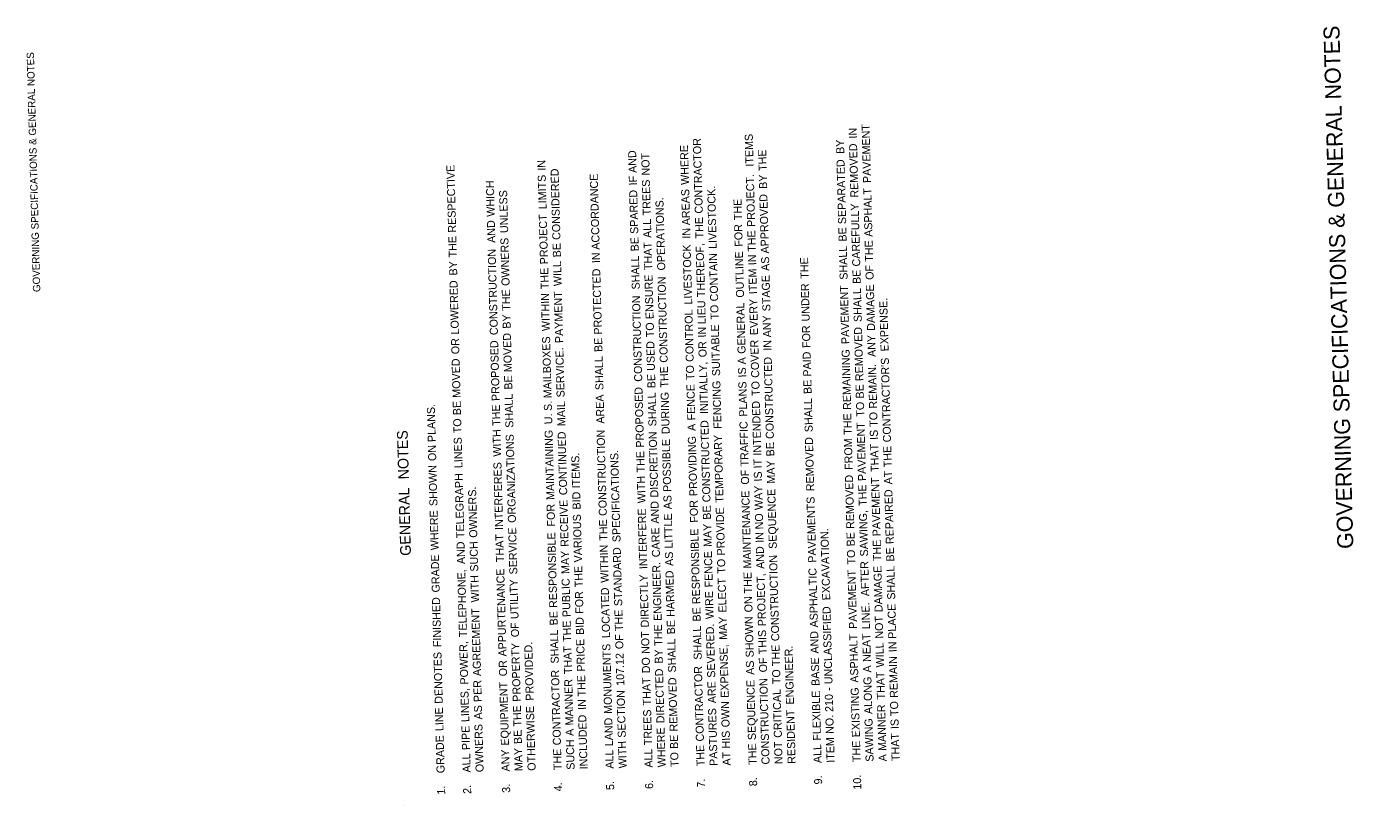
# Model space of a CAD drawing. Extents: x 1930579 to 1931706, y 595585 to 597808.
# Drawn here: x 1930711 to 1931706, y 597224 to 597808 of the extents above; entities that cross this region are included whole.
import ezdxf

# ---------------------------------------------------------------- set-up
doc = ezdxf.new("R2010")
doc.units = 0
for name, color, linetype in [('Default', 7, 'Continuous'), ('R_Annotation', 7, 'Continuous'), ('R_Border', 7, 'Continuous')]:
    doc.layers.add(name, color=color, linetype=linetype)

msp = doc.modelspace()

# ---------------------------------------------------------------- linework, layer by layer
at = {"layer": 'Default'}
msp.add_line((1930993.47, 597224.34), (1930993.47, 597224.34), dxfattribs=at)

# ---------------------------------------------------------------- texts
for s, height, p in [(' PAVEMENT', 6, (1931344.1, 597688.76)), (' CONTRACTOR', 6, (1931217.92, 597665.82)), ('  ITEMS', 6, (1931256.04, 597698.84)), (' BY', 6, (1931324, 597710.57)), (' IN', 6, (1931333.45, 597722.07)), (' AND', 6, (1931168.33, 597696.32)), (' NOT', 6, (1931178.14, 597694.36)), (' WHERE', 6, (1931207.58, 597687.37)), (' THE', 6, (1931265.82, 597697.82)), (' REMOVED', 6, (1931334.64, 597677.81)), (' RESPECTIVE', 6, (1931032.98, 597651.55)), (' IN', 6, (1931100.01, 597697.97)), (' SEPARATED', 6, (1931325.42, 597657.92)), (' LIMITS', 6, (1931100.79, 597669.08)), (' CONSIDERED', 6, (1931111.16, 597646.1)), (' ACCORDANCE', 6, (1931140.62, 597638.73)), (' IF', 6, (1931168.58, 597686.94)), (' TREES', 6, (1931178.94, 597664.53)), (' PROJECT.', 6, (1931257.2, 597655.8)), (' BY', 6, (1931266.19, 597684.38)), (' WHICH', 6, (1931061.92, 597663.46)), (' UNLESS', 6, (1931072, 597651.25)), (' SPARED', 6, (1931169.56, 597650.59)), (' AREAS', 6, (1931208.4, 597657.06)), (' LIVESTOCK.', 6, (1931228.38, 597639.37)), (' ASPHALT', 6, (1931345.18, 597648.4)), (' OPERATIONS.', 6, (1931189.8, 597623.19)), (' THE', 6, (1931247.31, 597660.92)), (' APPROVED', 6, (1931267.49, 597635.92)), (' CAREFULLY', 6, (1931336.02, 597626.18)), (' PROJECT', 6, (1931101.89, 597627.8)), (' ALL', 6, (1931179.39, 597647.59)), (' THE', 6, (1931218.42, 597647.17)), (' AND', 6, (1931062.45, 597643.89)), (' IN', 6, (1931208.67, 597647.04)), (' FOR', 6, (1931247.84, 597641.01)), (' THE', 6, (1931257.7, 597637.16)), (' BE', 6, (1931325.77, 597644.86)), (' THE', 6, (1931033.48, 597632.91)), (' OWNERS', 6, (1931073.07, 597611.65)), (' BE', 6, (1931111.51, 597633.04)), (' BE', 6, (1931169.91, 597637.53)), (' THAT', 6, (1931180.04, 597623.55)), (' LIVESTOCK', 6, (1931209.99, 597597.69)), (' THEREOF,', 6, (1931219.6, 597603.22)), (' SHALL', 6, (1931326.53, 597616.28)), (' THE', 6, (1931345.68, 597629.76)), (' CONSTRUCTION', 6, (1931064.31, 597574.73)), (' IN', 6, (1931140.88, 597628.71)), (' SHALL', 6, (1931170.68, 597608.94)), (' CONTAIN', 6, (1931229.44, 597600.01)), (' OUTLINE', 6, (1931248.87, 597602.81)), (' IN', 6, (1931257.97, 597627.14)), (' AS', 6, (1931267.84, 597622.85)), (' THE', 6, (1931297.25, 597617.01)), (' BY', 6, (1931033.84, 597619.46)), (' THE', 6, (1931102.4, 597609.16)), (' WILL', 6, (1931112.09, 597611.46)), (' PROTECTED', 6, (1931142.32, 597575.14)), (' ITEM', 6, (1931258.55, 597605.42)), (' BE', 6, (1931336.37, 597613.12)), (' OF', 6, (1931346.04, 597616.18)), (' LOWERED', 6, (1931035.03, 597575.21)), (' ENSURE', 6, (1931181.02, 597586.74)), (' CONSTRUCTION', 6, (1931191.66, 597554.04)), (' STAGE', 6, (1931268.65, 597592.56)), (' UNDER', 6, (1931298.11, 597584.99)), (' PAVEMENT', 6, (1931327.83, 597568.01)), (' DAMAGE', 6, (1931347.07, 597577.97)), (' THE', 6, (1931073.57, 597593)), (' WITHIN', 6, (1931103.24, 597577.73)), (' PAYMENT', 6, (1931113.23, 597568.78)), (' CONSTRUCTION', 6, (1931172.53, 597539.79)), (' EVERY', 6, (1931259.38, 597574.74)), (' SHALL', 6, (1931337.14, 597584.54)), (' EXPENSE.', 6, (1931357.24, 597562.55)), (' CONTROL', 6, (1931211.15, 597554.69)), (' LIEU', 6, (1931220.14, 597582.94)), (' TO', 6, (1931229.8, 597586.42)), (' GENERAL', 6, (1931250, 597560.73)), (' BY', 6, (1931073.93, 597579.56)), (' TO', 6, (1931181.39, 597573.15)), (' SUITABLE', 6, (1931230.94, 597544.02)), (' ANY', 6, (1931269.17, 597573.06)), (' FOR', 6, (1931298.65, 597565.09)), (' OR', 6, (1931035.43, 597560.43)), (' MOVED', 6, (1931074.8, 597546.94)), (' MAILBOXES', 6, (1931104.59, 597527.4)), (' BE', 6, (1931142.67, 597562.08)), (' IN', 6, (1931220.41, 597572.92)), (' REMOVED', 6, (1931338.33, 597540.28)), ('  ANY', 6, (1931347.66, 597556.15)), (' PROPOSED', 6, (1931065.63, 597525.35)), (' SERVICE.', 6, (1931114.33, 597528.06)), (' USED', 6, (1931182.07, 597547.98)), (' OR', 6, (1931220.81, 597558.13)), (' COVER', 6, (1931260.23, 597542.72)), (' IN', 6, (1931269.44, 597563.04)), (' PAID', 6, (1931299.22, 597543.65)), (' REMAINING', 6, (1931329.15, 597518.72)), (' MOVED', 6, (1931036.3, 597527.81)), (' SHALL', 6, (1931143.44, 597533.5)), (' TO', 6, (1931211.51, 597541.1)), (' INITIALLY,', 6, (1931221.95, 597515.57)), (' A', 6, (1931250.21, 597552.8)), (' CONSTRUCTED', 6, (1931271.22, 597496.9)), (' REMAIN.', 6, (1931348.64, 597519.63)), (" CONTRACTOR'S", 6, (1931359.07, 597494.34)), (' BE', 6, (1931075.16, 597533.88)), (' BE', 6, (1931182.42, 597534.92)), (' THE', 6, (1931192.16, 597535.4)), (' IS', 6, (1931250.47, 597542.99)), (' PROPOSED', 6, (1931173.86, 597490.41)), (' FENCE', 6, (1931212.32, 597510.81)), (' FENCING', 6, (1931232, 597504.5)), (' PLANS', 6, (1931251.26, 597513.62)), (' TO', 6, (1931260.6, 597529.13)), (' BE', 6, (1931299.57, 597530.59)), (' BE', 6, (1931338.68, 597527.22)), (' PLANS.', 6, (1931017.69, 597494.58)), (' BE', 6, (1931036.65, 597514.75)), (' THE', 6, (1931066.13, 597506.7)), (' SHALL', 6, (1931075.92, 597505.3)), (' S.', 6, (1931104.85, 597517.89)), (' MAIL', 6, (1931114.9, 597506.48)), (' AREA', 6, (1931144.12, 597508.34)), (' SHALL', 6, (1931183.18, 597506.34)), (' DURING', 6, (1931193.09, 597500.54)), (' INTENDED', 6, (1931261.8, 597484.41)), (' SHALL', 6, (1931300.34, 597502.01)), (' TO', 6, (1931339.04, 597513.63)), (' TO', 6, (1931037.02, 597501.16)), (' U.', 6, (1931105.11, 597507.91)), (' THE', 6, (1931329.65, 597500.08)), (' TO', 6, (1931349, 597506.04)), (' NOTES', 8, (1930997.57, 597465.89)), (' WITH', 6, (1931066.75, 597483.65)), (' MAINTAINING', 6, (1931106.64, 597451.17)), (' CONTINUED', 6, (1931116.29, 597454.78)), (' CONSTRUCTION', 6, (1931145.97, 597439.18)), (' A', 6, (1931212.54, 597502.88)), (' CONSTRUCTED', 6, (1931223.72, 597449.44)), (' TRAFFIC', 6, (1931252.27, 597476.24)), (' PAVEMENT', 6, (1931340.34, 597465.36)), (' IS', 6, (1931349.26, 597496.23)), (' LINES', 6, (1931037.72, 597475.05)), (' ORGANIZATIONS', 6, (1931077.84, 597434.03)), (' DISCRETION', 6, (1931184.61, 597453.02)), (' POSSIBLE', 6, (1931194.26, 597457.2)), (' PROVIDING', 6, (1931213.85, 597454.05)), (' TEMPORARY', 6, (1931233.49, 597449.15)), (' BE', 6, (1931271.57, 597483.84)), (' REMOVED', 6, (1931301.53, 597457.75)), (' FROM', 6, (1931330.36, 597473.71)), (' THAT', 6, (1931349.91, 597472.19)), (' ON', 6, (1931018.07, 597480.36)), (' ITEMS.', 6, (1931125.91, 597459.86)), (' SPECIFICATIONS.', 6, (1931156.25, 597419.57)), (' THE', 6, (1931174.36, 597471.76)), (' THE', 6, (1931359.57, 597475.7)), (' SHOWN', 6, (1931018.98, 597446.6)), (' INTERFERES', 6, (1931068.23, 597428.67)), (' OF', 6, (1931252.63, 597462.66)), (' IT', 6, (1931262.06, 597474.81)), (' IS', 6, (1931262.32, 597465)), (' MAY', 6, (1931272.12, 597463.42)), (' AT', 6, (1931359.91, 597462.83)), (' TELEGRAPH', 6, (1931039.13, 597422.64)), (' WITH', 6, (1931174.98, 597448.7)), (' REMOVED', 6, (1931331.55, 597429.45)), (' THE', 6, (1931340.84, 597446.72)), (' PAVEMENT', 6, (1931351.21, 597423.93)), ('GENERAL', 8, (1930999.03, 597411.59)), (' OWNERS.', 6, (1931048.88, 597422.86)), (' BID', 6, (1931126.34, 597444.01)), (' AS', 6, (1931194.61, 597444.13)), (' MAINTENANCE', 6, (1931254.32, 597399.78)), (' WAY', 6, (1931262.89, 597443.65)), (' SEQUENCE', 6, (1931273.43, 597414.5)), (' PAVEMENTS', 6, (1931302.97, 597404.16)), (' REPAIRED', 6, (1931361.11, 597418.1)), (' WHERE', 6, (1931019.87, 597413.52)), (' FOR', 6, (1931107.17, 597431.27)), (' RECEIVE', 6, (1931117.33, 597416.1)), (' INTERFERE', 6, (1931176.3, 597399.33)), (' AND', 6, (1931185.14, 597433.44)), (' FOR', 6, (1931214.38, 597434.14)), (' BE', 6, (1931224.08, 597436.38)), (' PROVIDE', 6, (1931234.55, 597409.55)), (' SAWING,', 6, (1931341.86, 597408.82)), (' VARIOUS', 6, (1931127.4, 597404.4)), (' THE', 6, (1931146.47, 597420.54)), (' LITTLE', 6, (1931195.39, 597414.78)), (' MAY', 6, (1931224.62, 597415.95)), (' NO', 6, (1931263.28, 597429.12)), (' THAT', 6, (1931068.87, 597404.63)), (' SERVICE', 6, (1931078.87, 597395.36)), (' RESPONSIBLE', 6, (1931108.81, 597370.23)), (' CARE', 6, (1931185.82, 597408.27)), (' RESPONSIBLE', 6, (1931216.02, 597373.11)), (' IN', 6, (1931263.55, 597419.1)), (' EXCAVATION.', 6, (1931313.48, 597375.94)), (' BE', 6, (1931331.9, 597416.39)), (' AND', 6, (1931039.65, 597403.06)), (' SUCH', 6, (1931049.56, 597397.46)), (' MAY', 6, (1931117.88, 597395.68)), (' WITHIN', 6, (1931147.32, 597389.11)), (' STANDARD', 6, (1931157.54, 597371.59)), (' FENCE', 6, (1931225.44, 597385.66)), (' AND', 6, (1931264.08, 597399.53)), (' TO', 6, (1931332.27, 597402.8)), (' THE', 6, (1931351.71, 597405.28)), (' BE', 6, (1931361.47, 597405.04)), (' GRADE', 6, (1931020.72, 597381.84)), (' ENGINEER.', 6, (1931187.1, 597360.58)), (' AS', 6, (1931195.75, 597401.71)), (' TO', 6, (1931234.91, 597395.95)), (' CONSTRUCTION', 6, (1931275.29, 597345.34)), ('  AFTER', 6, (1931342.72, 597376.81)), (' TELEPHONE,', 6, (1931041.12, 597348.39)), (' WITH', 6, (1931050.18, 597374.4)), (' APPURTENANCE', 6, (1931070.77, 597333.82)), (' THE', 6, (1931127.9, 597385.75)), (' DIRECTLY', 6, (1931177.48, 597355.62)), (' HARMED', 6, (1931196.77, 597363.51)), (' THE', 6, (1931254.82, 597381.14)), (' PROJECT,', 6, (1931265.23, 597356.5)), (' ASPHALTIC', 6, (1931304.27, 597355.6)), (' PAVEMENT', 6, (1931333.56, 597354.53)), (' DAMAGE', 6, (1931352.73, 597367.08)), (' SHALL', 6, (1931362.23, 597376.46)), (' UTILITY', 6, (1931079.77, 597361.9)), (' PUBLIC', 6, (1931118.75, 597363.41)), (' LOCATED', 6, (1931148.43, 597347.65)), (' WIRE', 6, (1931226.07, 597361.9)), (' ELECT', 6, (1931235.7, 597366.78)), (' FINISHED', 6, (1931021.82, 597340.84)), (' FOR', 6, (1931128.43, 597365.85)), (' ON', 6, (1931255.2, 597366.92)), (' LINE.', 6, (1931343.32, 597354.26)), (' PLACE', 6, (1931363.02, 597347.1)), (' AGREEMENT', 6, (1931051.66, 597319.15)), (' BE', 6, (1931109.16, 597357.17)), (' BID', 6, (1931128.86, 597350)), (' THE', 6, (1931158.04, 597352.95)), (' BE', 6, (1931216.37, 597360.05)), (' MAY', 6, (1931236.25, 597346.36)), (' SHOWN', 6, (1931256.11, 597333.16)), (' UNCLASSIFIED', 6, (1931315.17, 597313.06)), (' NOT', 6, (1931353.26, 597347.23)), (' OF', 6, (1931080.14, 597348.32)), (' SHALL', 6, (1931109.93, 597328.59)), (' THE', 6, (1931119.25, 597344.77)), (' THE', 6, (1931187.6, 597341.93)), (' BE', 6, (1931197.12, 597350.45)), (' SHALL', 6, (1931217.14, 597331.47)), (' SEVERED.', 6, (1931227.26, 597317.92)), (' THIS', 6, (1931265.8, 597335.52)), (' POWER,', 6, (1931042.08, 597312.81)), (' PROPERTY', 6, (1931081.43, 597299.94)), (' PROVIDED.', 6, (1931091.17, 597300.71)), (' PRICE', 6, (1931129.6, 597322.51)), (' MONUMENTS', 6, (1931149.95, 597290.82)), (' OF', 6, (1931158.4, 597339.36)), (' NOT', 6, (1931178.01, 597335.77)), (' SHALL', 6, (1931197.89, 597321.86)), (' AND', 6, (1931304.8, 597336.02)), (' ASPHALT', 6, (1931334.64, 597314.18)), (' NEAT', 6, (1931343.98, 597329.74)), (' WILL', 6, (1931353.84, 597325.65)), (' IN', 6, (1931363.29, 597337.08)), (' DENOTES', 6, (1931022.95, 597298.44)), (' THAT', 6, (1931119.89, 597320.73)), (' 107.12', 6, (1931159.14, 597311.86)), (' DO', 6, (1931178.4, 597321.25)), (' BY', 6, (1931187.96, 597328.49)), (' EXPENSE,', 6, (1931237.41, 597302.85)), (' THE', 6, (1931275.79, 597326.7)), (' ENGINEER.', 6, (1931286.32, 597297.85)), (' BASE', 6, (1931305.45, 597311.78)), (' REMAIN', 6, (1931364.21, 597302.84)), (' OR', 6, (1931071.17, 597319.03)), (' CONTRACTOR', 6, (1931111.57, 597267.24)), (' DIRECTED', 6, (1931189.16, 597283.77)), (' CONTRACTOR', 6, (1931218.78, 597270.12)), (' AS', 6, (1931256.46, 597320.09)), (' OF', 6, (1931266.16, 597321.94)), (' TO', 6, (1931276.15, 597313.11)), (' A', 6, (1931344.19, 597321.81)), (' PER', 6, (1931052.18, 597299.7)), (' EQUIPMENT', 6, (1931072.56, 597267.05)), (' MANNER', 6, (1931120.93, 597282.19)), (' THE', 6, (1931130.1, 597303.86)), (' THAT', 6, (1931179.04, 597297.2)), (' REMOVED', 6, (1931199.08, 597277.61)), (' ARE', 6, (1931227.77, 597298.81)), (' SEQUENCE', 6, (1931257.77, 597271.17)), ('CONSTRUCTION', 6, (1931267.96, 597255.11)), (' ALONG', 6, (1931345.03, 597290.67)), (' THAT', 6, (1931354.49, 597301.61)), (' LINES,', 6, (1931042.83, 597284.69)), (' SECTION', 6, (1931160.19, 597272.97)), (' CRITICAL', 6, (1931277.23, 597272.9)), (' FLEXIBLE', 6, (1931306.55, 597270.77)), (' 210', 6, (1931315.72, 597292.3)), (' -', 6, (1931315.3, 597308.2)), (' EXISTING', 6, (1931335.74, 597273.26)), (' LINE', 6, (1931023.5, 597277.93)), (' AS', 6, (1931052.53, 597286.63)), (' THE', 6, (1931081.94, 597281.3)), ('OTHERWISE', 6, (1931092.52, 597250.4)), (' IN', 6, (1931130.37, 597293.84)), (' TREES', 6, (1931179.84, 597267.37)), ('PASTURES', 6, (1931228.97, 597254.07)), (' OWN', 6, (1931238.01, 597280.73)), ('RESIDENT', 6, (1931287.45, 597255.64)), (' MANNER', 6, (1931355.52, 597263.07)), (' TO', 6, (1931364.57, 597289.25)), ('INCLUDED', 6, (1931131.5, 597251.45)), (' LAND', 6, (1931150.61, 597266.58)), (' NO.', 6, (1931316.17, 597275.81)), ('SAWING', 6, (1931345.93, 597257.21)), (' IS', 6, (1931364.84, 597279.44)), ('GRADE', 6, (1931024.29, 597248.57)), (' PIPE', 6, (1931043.39, 597263.71)), ('OWNERS', 6, (1931053.53, 597249.36)), (' BE', 6, (1931082.29, 597268.24)), (' A', 6, (1931121.14, 597274.26)), ('WHERE', 6, (1931189.98, 597253.02)), (' BE', 6, (1931199.43, 597264.55)), (' HIS', 6, (1931238.43, 597264.87)), ('THAT', 6, (1931365.42, 597257.73)), ('ANY', 6, (1931073.03, 597249.88)), ('MAY', 6, (1931082.77, 597250.14)), ('THE', 6, (1931112.01, 597250.93)), ('SUCH', 6, (1931121.76, 597251.19)), ('ALL', 6, (1931151, 597251.97)), ('WITH', 6, (1931160.74, 597252.24)), ('ALL', 6, (1931180.24, 597252.76)), ('THE', 6, (1931219.22, 597253.81)), ('THE', 6, (1931258.21, 597254.85)), ('NOT', 6, (1931277.7, 597255.38)), ('ALL', 6, (1931306.94, 597256.16)), ('ITEM', 6, (1931316.69, 597256.42)), ('THE', 6, (1931336.18, 597256.95)), ('ALL', 6, (1931043.79, 597249.1)), ('TO', 6, (1931199.73, 597253.28)), ('AT', 6, (1931238.72, 597254.33)), ('A', 6, (1931355.67, 597257.47)), ('9.', 6, (1931307.37, 597240.16)), ('10.', 6, (1931336.74, 597236.29)), ('1.', 6, (1931024.72, 597232.57)), ('2.', 6, (1931044.22, 597233.1)), ('3.', 6, (1931073.45, 597233.88)), ('4.', 6, (1931112.44, 597234.93)), ('5.', 6, (1931151.43, 597235.97)), ('6.', 6, (1931180.67, 597236.76)), ('7.', 6, (1931219.65, 597237.81)), ('8.', 6, (1931258.64, 597238.85))]:
    msp.add_text(s, height=height, rotation=91.53769, dxfattribs=at).set_placement(p)
at = {"layer": 'R_Annotation'}
msp.add_text('GOVERNING SPECIFICATIONS & GENERAL NOTES', height=12, rotation=91.53769, dxfattribs=at).set_placement((1931705.66, 597416.78))
at = {"layer": 'R_Border'}
msp.add_text('GOVERNING SPECIFICATIONS & GENERAL NOTES', height=5.5, rotation=91.53769, dxfattribs=at).set_placement((1930721.15, 597609.23))

doc.saveas('drawing.dxf')
